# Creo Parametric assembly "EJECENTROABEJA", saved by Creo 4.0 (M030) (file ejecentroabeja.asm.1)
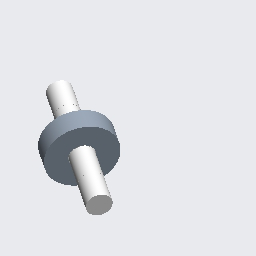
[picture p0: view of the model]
Units: millimeter Newton Second (mmNs); MM, TONNE, SECS

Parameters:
  MODELED_BY = "aj"

Created from: MMNS_ASM_DESIGN.ASM

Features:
  1. datum plane "ASM_RIGHT"
  2. datum plane "ASM_TOP"
  3. datum plane "ASM_FRONT"
  4. coordinate system
  5. component "EJERUEDASCENTROABEJA"
  6. component "RODAMIENTOABEJA"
